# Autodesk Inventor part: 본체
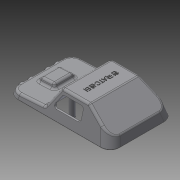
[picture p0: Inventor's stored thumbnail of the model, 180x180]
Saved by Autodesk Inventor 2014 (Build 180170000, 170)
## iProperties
Created: 2015-05
Part Number: 본체
Material: 일반
Document SubType Name: Modeling
Designer: 학생용
Density: 1 g/cm^3
Appearance: 기본값
Mass: 28.5346 g
Surface Area: 298.948 cm^2
Volume: 28.5346 cm^3
Author: 학생용
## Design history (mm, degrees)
sketch "스케치1"
  geometry: L1 (0, 0)-(-122, 0); L2 (-122, 0)-(-120.392, 6); L3 (-120.392, 6)-(-80, 8.117); L4 (-80, 8.117)-(-65.701, 31); L5 (-65.701, 31)-(-32.947, 31); L6 (-32.947, 31)-(-2.947, 11); L7 (-2.947, 11)-(0, 0); 1 further point
  constraints: 14 end point, 2 horizontal, 1 coincident
  dimensions: "d0" = 122 distance of L1.start L1.end; "d1" = 105 deg angle of L2 L1; "d2" = 105 deg angle of L1 L7; "d3" = 125 deg angle of L4 L3; "d4" = 6 vertical distance of L1.end L2.end; "d5" = 31 distance from line of L1 L5.end; "d6" = 30 horizontal distance of L6.end L5.end; "d7" = 42 horizontal distance of L1.end L3.end; "d8" = 20 vertical distance of L6.end L5.end; "d9" = 3 deg angle of L1 L3
extrude "돌출1" new body sketch "스케치1" distance "d10" = 76; taper "d11" = 0 deg
node "작업 평면1"
sketch "스케치3"
  geometry: L1 (0, 0)-(6, 0) reference; L2 (6, 0)-(6, -76) reference; L3 (0, -76)-(6, -76) reference; L4 (0, 0)-(0, -76) reference; L5 (37.372, -76)-(37.372, -65.986); L6 (37.372, -65.986)-(0, -76); L7 (0, -76)-(37.372, -76); L8 (0, 0)-(37.372, -10.014); L9 (0, 0)-(37.372, 0); L10 (37.372, 0)-(37.372, -10.014); 1 further point
  constraints: 12 end point, 2 horizontal, 1 coincident, 1 parallel, 1 vertical, 1 vertical alignment
  dimensions: "d15" = 105 deg angle of L4 L8; "d16" = 105 deg angle of L6 L4; "d17" = 31.37205 distance between parallel lines of L5 L2
extrude "돌출2" cut sketch "스케치3" stored distance "d18" = 76; taper "d19" = 0 deg
sketch "스케치4"
  geometry: L1 (0, 0)-(0, 72.785) reference; L2 (9.08, 49.392)-(29.08, 49.392); L3 (29.08, 49.392)-(29.08, 23.392); L4 (29.08, 23.392)-(9.08, 23.392); L5 (9.08, 23.392)-(9.08, 49.392); L6 (9.08, 49.392)-(29.08, 23.392); L7 (29.08, 49.392)-(9.08, 23.392); L8 (-1.92, -1.608)-(-1.92, 74.392) reference; 4 further points
  constraints: 12 end point, 4 midpoint, 2 parallel, 1 horizontal, 1 horizontal alignment, 1 perpendicular
  dimensions: "d20" = 20 distance of L2.start L2.end; "d21" = 26 distance of L2.end L3.end; "d22" = 11 distance between parallel lines of L5 L8
extrude "돌출3" join sketch "스케치4" distance "d23" = 5; taper "d24" = -20 deg
fillet "모깎기1" dims "d25" = 12
fillet "모깎기2" dims "d26" = 12
feature "쉘1" dims "d28" = 2
node "작업 평면2"
sketch "스케치5"
  geometry: L1 (-72.303, 11)-(-38.303, 11); L2 (-38.303, 11)-(-38.303, 26); L3 (-38.303, 26)-(-62.929, 26); L4 (-62.929, 26)-(-72.303, 11); L5 (-33.856, 31)-(-64.038, 31) reference; L6 (-66.582, 29.59)-(-79.172, 9.441) reference; L7 (-14.472, 18.683)-(-32.192, 30.496) reference; 1 further point
  constraints: 8 end point, 2 horizontal, 1 parallel, 1 vertical
  dimensions: "d32" = 34 distance of L1.start L1.end; "d33" = 15 distance between parallel lines of L1 L3; "d34" = 5 distance between parallel lines of L3 L5; "d36" = 5 distance from line of L6 L3.end
extrude "돌출4" cut sketch "스케치5" stored distance "d40" = 5; taper "d41" = 0 deg
fillet "모깎기4" dims "d42" = 3
sketch "스케치8" dims "d55" = 6
  geometry: L1 (12.179, 38.008)-(12.179, 14.809) reference; L2 (12.179, 38.008)-(12.179, 26.409); L3 (29.355, 14.809)-(29.355, 38.008) reference; L4 (12.179, 26.409)-(29.355, 26.409); L5 (100.767, 23.409)-(124.378, 23.409); L6 (29.355, 26.409)-(20.767, 26.409); C1 r 3 at (20.767, 26.409); C2 r 3 at (60.767, 4.409); C3 r 3 at (60.767, 48.409); 4 further points
  constraints: 8 end point, 5 midpoint, 3 centre point, 3 horizontal, 2 vertical alignment, 1 coincident, 1 horizontal alignment, 1 vertical, 2 other
  dimensions: "d52" = 6 diameter of C1; "d53" = 6 diameter of C2; "d54" = 6 diameter of C3; "d57" = 11.5995 distance of L1.start L2.end; "d58" = 8.588 distance of L6.start L6.end; "d59" = 80 distance of point (100.767, 26.409) C1.centre; "d60" = 40 horizontal distance of C2.centre L6.end; "d61" = 22 vertical distance of C2.centre L6.end; "d62" = 44 distance of C2.centre C3.centre
fillet "모깎기5" dims "d56" = 3
extrude "돌출5" join sketch "스케치8" stored distance "d63" = 5; taper "d64" = 0 deg
node "작업 평면3"
sketch "스케치9"
  geometry: L1 (-109.821, 4.551)-(-118.837, 4.079) reference; L2 (-118.837, 4.079)-(-119.929, 0) reference; L3 (-119.929, 0)-(-122, 0) reference; L4 (-122, 0)-(-120.956, 3.895) reference; L5 (-118.216, 6.114)-(-113.422, 6.365) reference; L6 (-110.71, 8.484)-(-110.383, 9.555) reference; L7 (-107.671, 11.674)-(-95.528, 12.31) reference; L8 (-92.61, 10.486)-(-92.172, 9.456) reference; L9 (-89.254, 7.632)-(-81.56, 8.035) reference; L10 (-79.172, 9.441)-(-66.582, 29.59) reference; L11 (-64.038, 31)-(-33.856, 31) reference; L12 (-32.192, 30.496)-(-3.888, 11.627) reference; L13 (-2.655, 9.908)-(0, 0) reference; L14 (0, 0)-(-2.071, 0) reference; L15 (-2.071, 0)-(-4.684, 9.754) reference; L16 (-4.684, 9.754)-(-18.233, 18.787) reference; L17 (-18.233, 18.787)-(-18.233, 0) reference; L18 (-18.233, 0)-(-24.233, 0) reference; L19 (-24.233, 0)-(-24.233, 22.787) reference; L20 (-24.233, 22.787)-(-33.553, 29) reference; L21 (-33.553, 29)-(-64.592, 29) reference; L22 (-64.592, 29)-(-78.856, 6.174) reference; L23 (-78.856, 6.174)-(-92.645, 5.451) reference; L24 (-92.645, 5.451)-(-94.725, 10.349) reference; L25 (-94.725, 10.349)-(-98.233, 10.165) reference; L26 (-98.233, 10.165)-(-98.233, 0) reference; L27 (-98.233, 0)-(-104.233, 0) reference; L28 (-104.233, 0)-(-104.233, 9.851) reference; L29 (-104.233, 9.851)-(-108.265, 9.64) reference; L30 (-108.265, 9.64)-(-109.821, 4.551) reference; L31 (-106.233, 2)-(-96.233, 2); L32 (-107.587, 9.675)-(-106.233, 2); L33 (-94.761, 10.347)-(-96.233, 2); L34 (-107.587, 9.675)-(-104.233, 9.851); L35 (-94.725, 10.349)-(-107.587, 9.675); L36 (-26.233, 2)-(-16.233, 2); A1 r 3 centre (-118.059, 3.118) between (-118.216, 6.114) and (-120.956, 3.895) reference; A2 r 3 centre (-113.579, 9.361) between (-113.422, 6.365) and (-110.71, 8.484) reference; A3 r 3 centre (-107.514, 8.678) between (-107.671, 11.674) and (-110.383, 9.555) reference; A4 r 3 centre (-95.371, 9.314) between (-92.61, 10.486) and (-95.528, 12.31) reference; A5 r 3 centre (-89.411, 10.628) between (-92.172, 9.456) and (-89.254, 7.632) reference; A6 r 3 centre (-81.717, 11.031) between (-81.56, 8.035) and (-79.172, 9.441) reference; A7 r 3 centre (-64.038, 28) between (-64.038, 31) and (-66.582, 29.59) reference; A8 r 3 centre (-33.856, 28) between (-32.192, 30.496) and (-33.856, 31) reference; A9 r 3 centre (-5.553, 9.131) between (-2.655, 9.908) and (-3.888, 11.627) reference; 6 further points
  constraints: 12 end point, 4 midpoint, 4 vertical alignment, 2 horizontal, 2 point on line
  dimensions: "d66" = 10 distance of L31.end L31.start; "d67" = 2 distance between parallel lines of L27 L31; "d68" = 20 deg angle of L33 L32; "d69" = 80 deg angle of L14 L33; "d70" = 11.03446 distance from line of point (-101.233, 11.034) L14; "d71" = 10 distance of L36.start L36.end; "d73" = 2 distance between parallel lines of L18 L36
extrude "돌출6" join sketch "스케치9" stored distance "d78" = 2; taper "d79" = 0 deg
sketch "스케치10"
  geometry: L1 (-109.821, 4.551)-(-118.837, 4.079) reference; L2 (-118.837, 4.079)-(-119.929, 0) reference; L3 (-119.929, 0)-(-122, 0) reference; L4 (-122, 0)-(-120.956, 3.895) reference; L5 (-118.216, 6.114)-(-113.422, 6.365) reference; L6 (-110.71, 8.484)-(-110.383, 9.555) reference; L7 (-107.671, 11.674)-(-95.528, 12.31) reference; L8 (-92.61, 10.486)-(-92.172, 9.456) reference; L9 (-89.254, 7.632)-(-81.56, 8.035) reference; L10 (-79.172, 9.441)-(-66.582, 29.59) reference; L11 (-64.038, 31)-(-33.856, 31) reference; L12 (-32.192, 30.496)-(-3.888, 11.627) reference; L13 (-2.655, 9.908)-(0, 0) reference; L14 (0, 0)-(-2.071, 0) reference; L15 (-2.071, 0)-(-4.684, 9.754) reference; L16 (-4.684, 9.754)-(-18.233, 18.787) reference; L17 (-18.233, 18.787)-(-18.233, 0) reference; L18 (-18.233, 0)-(-24.233, 0) reference; L19 (-24.233, 0)-(-24.233, 22.787) reference; L20 (-24.233, 22.787)-(-33.553, 29) reference; L21 (-33.553, 29)-(-64.592, 29) reference; L22 (-64.592, 29)-(-78.856, 6.174) reference; L23 (-78.856, 6.174)-(-92.645, 5.451) reference; L24 (-92.645, 5.451)-(-94.725, 10.349) reference; L25 (-94.725, 10.349)-(-94.761, 10.347) reference; L26 (-94.761, 10.347)-(-96.233, 2) reference; L27 (-96.233, 2)-(-98.233, 2) reference; L28 (-98.233, 2)-(-98.233, 0) reference; L29 (-98.233, 0)-(-104.233, 0) reference; L30 (-104.233, 0)-(-104.233, 2) reference; L31 (-104.233, 2)-(-106.233, 2) reference; L32 (-106.233, 2)-(-107.587, 9.675) reference; L33 (-107.587, 9.675)-(-108.265, 9.64) reference; L34 (-108.265, 9.64)-(-109.821, 4.551) reference; L35 (-26.233, 2)-(-16.233, 2); L36 (-16.233, 2)-(-13.795, 15.828); L37 (-26.233, 2)-(-30.653, 27.067); L38 (-30.653, 27.067)-(-13.795, 15.828); A1 r 3 centre (-118.059, 3.118) between (-118.216, 6.114) and (-120.956, 3.895) reference; A2 r 3 centre (-113.579, 9.361) between (-113.422, 6.365) and (-110.71, 8.484) reference; A3 r 3 centre (-107.514, 8.678) between (-107.671, 11.674) and (-110.383, 9.555) reference; A4 r 3 centre (-95.371, 9.314) between (-92.61, 10.486) and (-95.528, 12.31) reference; A5 r 3 centre (-89.411, 10.628) between (-92.172, 9.456) and (-89.254, 7.632) reference; A6 r 3 centre (-81.717, 11.031) between (-81.56, 8.035) and (-79.172, 9.441) reference; A7 r 3 centre (-64.038, 28) between (-64.038, 31) and (-66.582, 29.59) reference; A8 r 3 centre (-33.856, 28) between (-32.192, 30.496) and (-33.856, 31) reference; A9 r 3 centre (-5.553, 9.131) between (-2.655, 9.908) and (-3.888, 11.627) reference; 4 further points
  constraints: 8 end point, 4 point on line, 2 midpoint, 1 horizontal, 1 horizontal alignment, 1 vertical alignment
  dimensions: "d80" = 10 distance of L35.start L35.end; "d81" = 2 distance between parallel lines of L18 L35; "d83" = 20 deg angle of L37 L36; "d84" = 80 deg angle of L35 L36
extrude "돌출7" join sketch "스케치10" stored distance "d85" = 2; taper "d86" = 0 deg
hole "구멍1" diameter "d89" = 3.242; stored, may be unused: countersink angle "d93" = 90 deg, drill point angle "d95" = 118 deg; dims "d87" = 10, "d88" = 10, "d90" = 9, "d91" = 4, "d92" = 2, "d94" = 11
hole "구멍2" diameter "d98" = 3.242; stored, may be unused: countersink angle "d102" = 90 deg, drill point angle "d104" = 118 deg; dims "d96" = 10, "d97" = 10, "d99" = 9, "d100" = 4, "d101" = 2, "d103" = 11
node "작업 평면4"
sketch "스케치11"
  geometry: L1 (0, -48)-(0, -28); A1 r 4 centre (0, -59) between (0, -63) and (0, -55); A2 r 4 centre (0, -48) between (0, -52) and (0, -44); A3 r 4 centre (0, -28) between (0, -32) and (0, -24); A4 r 4 centre (0, -17) between (0, -21) and (0, -13); 4 further points
  constraints: 8 point on circle, 4 centre point, 3 equal radius, 3 vertical alignment, 2 coincident, 2 end point, 1 midpoint, 10 other
  dimensions: "d106" = 8 diameter of A1; "d107" = 11 distance of A2.centre A1.centre; "d108" = 11 distance of A4.centre A3.centre; "d109" = 20 distance of A2.centre A3.centre
extrude "돌출8" join sketch "스케치11" stored distance "d111" = 0; taper "d112" = 0 deg
chamfer "모따기1" distance "d113" = 1; stored, may be unused: second distance "d114" = 2, angle "d115" = 45 deg
sketch "스케치12"
  geometry: L1 (-12.591, 13)-(-13.591, 14) reference; L2 (-12.591, 13)-(-11.591, 13) reference; L3 (-11.591, 13)-(-11.591, 11.591) reference; L4 (98.818, 0)-(0, 0) reference; L5 (110.409, 64.409)-(110.409, 11.591) reference; L6 (98.818, 76)-(0, 76) reference; L7 (-11.591, 64.409)-(-11.591, 63) reference; L8 (-12.591, 63)-(-11.591, 63) reference; L9 (-13.591, 62)-(-12.591, 63) reference; L10 (-13.591, 62)-(-13.591, 56) reference; L11 (-12.591, 55)-(-13.591, 56) reference; L12 (-12.591, 55)-(-11.591, 55) reference; L13 (-11.591, 55)-(-11.591, 52) reference; L14 (-12.591, 52)-(-11.591, 52) reference; L15 (-13.591, 51)-(-12.591, 52) reference; L16 (-13.591, 51)-(-13.591, 45) reference; L17 (-12.591, 44)-(-13.591, 45) reference; L18 (-12.591, 44)-(-11.591, 44) reference; L19 (-11.591, 44)-(-11.591, 32) reference; L20 (-12.591, 32)-(-11.591, 32) reference; L21 (-13.591, 31)-(-12.591, 32) reference; L22 (-13.591, 31)-(-13.591, 25) reference; L23 (-12.591, 24)-(-13.591, 25) reference; L24 (-12.591, 24)-(-11.591, 24) reference; L25 (-11.591, 24)-(-11.591, 21) reference; L26 (-12.591, 21)-(-11.591, 21) reference; L27 (-13.591, 20)-(-12.591, 21) reference; L28 (-13.591, 20)-(-13.591, 14) reference; L29 (0, 75)-(98.818, 75); L30 (109.409, 64.409)-(109.409, 11.591); L31 (98.818, 1)-(0, 1); L32 (-10.591, 11.591)-(-10.591, 14); L33 (-10.591, 14)-(-12.177, 14); L34 (-12.177, 14)-(-12.591, 14.414); L35 (-12.591, 14.414)-(-12.591, 19.586); L36 (-12.591, 19.586)-(-12.177, 20); L37 (-12.177, 20)-(-10.591, 20); L38 (-10.591, 20)-(-10.591, 25); L39 (-10.591, 25)-(-12.177, 25); L40 (-12.177, 25)-(-12.591, 25.414); L41 (-12.591, 25.414)-(-12.591, 30.586); L42 (-12.591, 30.586)-(-12.177, 31); L43 (-12.177, 31)-(-10.591, 31); L44 (-10.591, 31)-(-10.591, 45); L45 (-10.591, 45)-(-12.177, 45); L46 (-12.177, 45)-(-12.591, 45.414); L47 (-12.591, 45.414)-(-12.591, 50.586); L48 (-12.591, 50.586)-(-12.177, 51); L49 (-12.177, 51)-(-10.591, 51); L50 (-10.591, 51)-(-10.591, 56); L51 (-10.591, 56)-(-12.177, 56); L52 (-12.177, 56)-(-12.591, 56.414); L53 (-12.591, 56.414)-(-12.591, 61.586); L54 (-12.591, 61.586)-(-12.177, 62); L55 (-12.177, 62)-(-10.591, 62); L56 (-10.591, 62)-(-10.591, 64.409); 5 further points; 4 other entities
  constraints: 56 end point, 7 parallel, 40 other
  dimensions: "d116" = 1 distance between parallel lines of L29 L6
extrude "돌출9" cut sketch "스케치12" distance "d117" = 1; taper "d118" = 0 deg
sketch "스케치13"
  geometry: L1 (0, 0)-(0, 54.783) reference; L2 (0, 54.783)-(30.182, 54.783) reference; 4 further points
  constraints: 2 midpoint, 1 horizontal alignment, 1 vertical alignment, 1 other
feature "엠보싱1" sketch "스케치13" dims "d0" = 122, "d1" = 105 deg, "d2" = 105 deg, "d3" = 125 deg, "d4" = 6, "d5" = 31, "d6" = 30, "d7" = 42, "d8" = 20, "d9" = 3 deg, "d17" = 31.37205, "d119" = 0.5, "d120" = 0
hole "구멍3" diameter "d123" = 3.242; stored, may be unused: countersink angle "d127" = 90 deg, drill point angle "d129" = 118 deg; dims "d121" = 10, "d122" = 10, "d124" = 9, "d125" = 4, "d126" = 2, "d128" = 11
hole "구멍4" diameter "d132" = 3.242; stored, may be unused: countersink angle "d136" = 90 deg, drill point angle "d138" = 118 deg; dims "d130" = 10, "d131" = 10, "d133" = 9, "d134" = 4, "d135" = 2, "d137" = 11
node "솔리드1"
node "투영된 루프1"
node "절단 모서리 투영1"
node "절단 모서리 투영2"
other parameters: "d14" = -133, "d29" = 5.5, "d65" = -38, "d105" = -124
